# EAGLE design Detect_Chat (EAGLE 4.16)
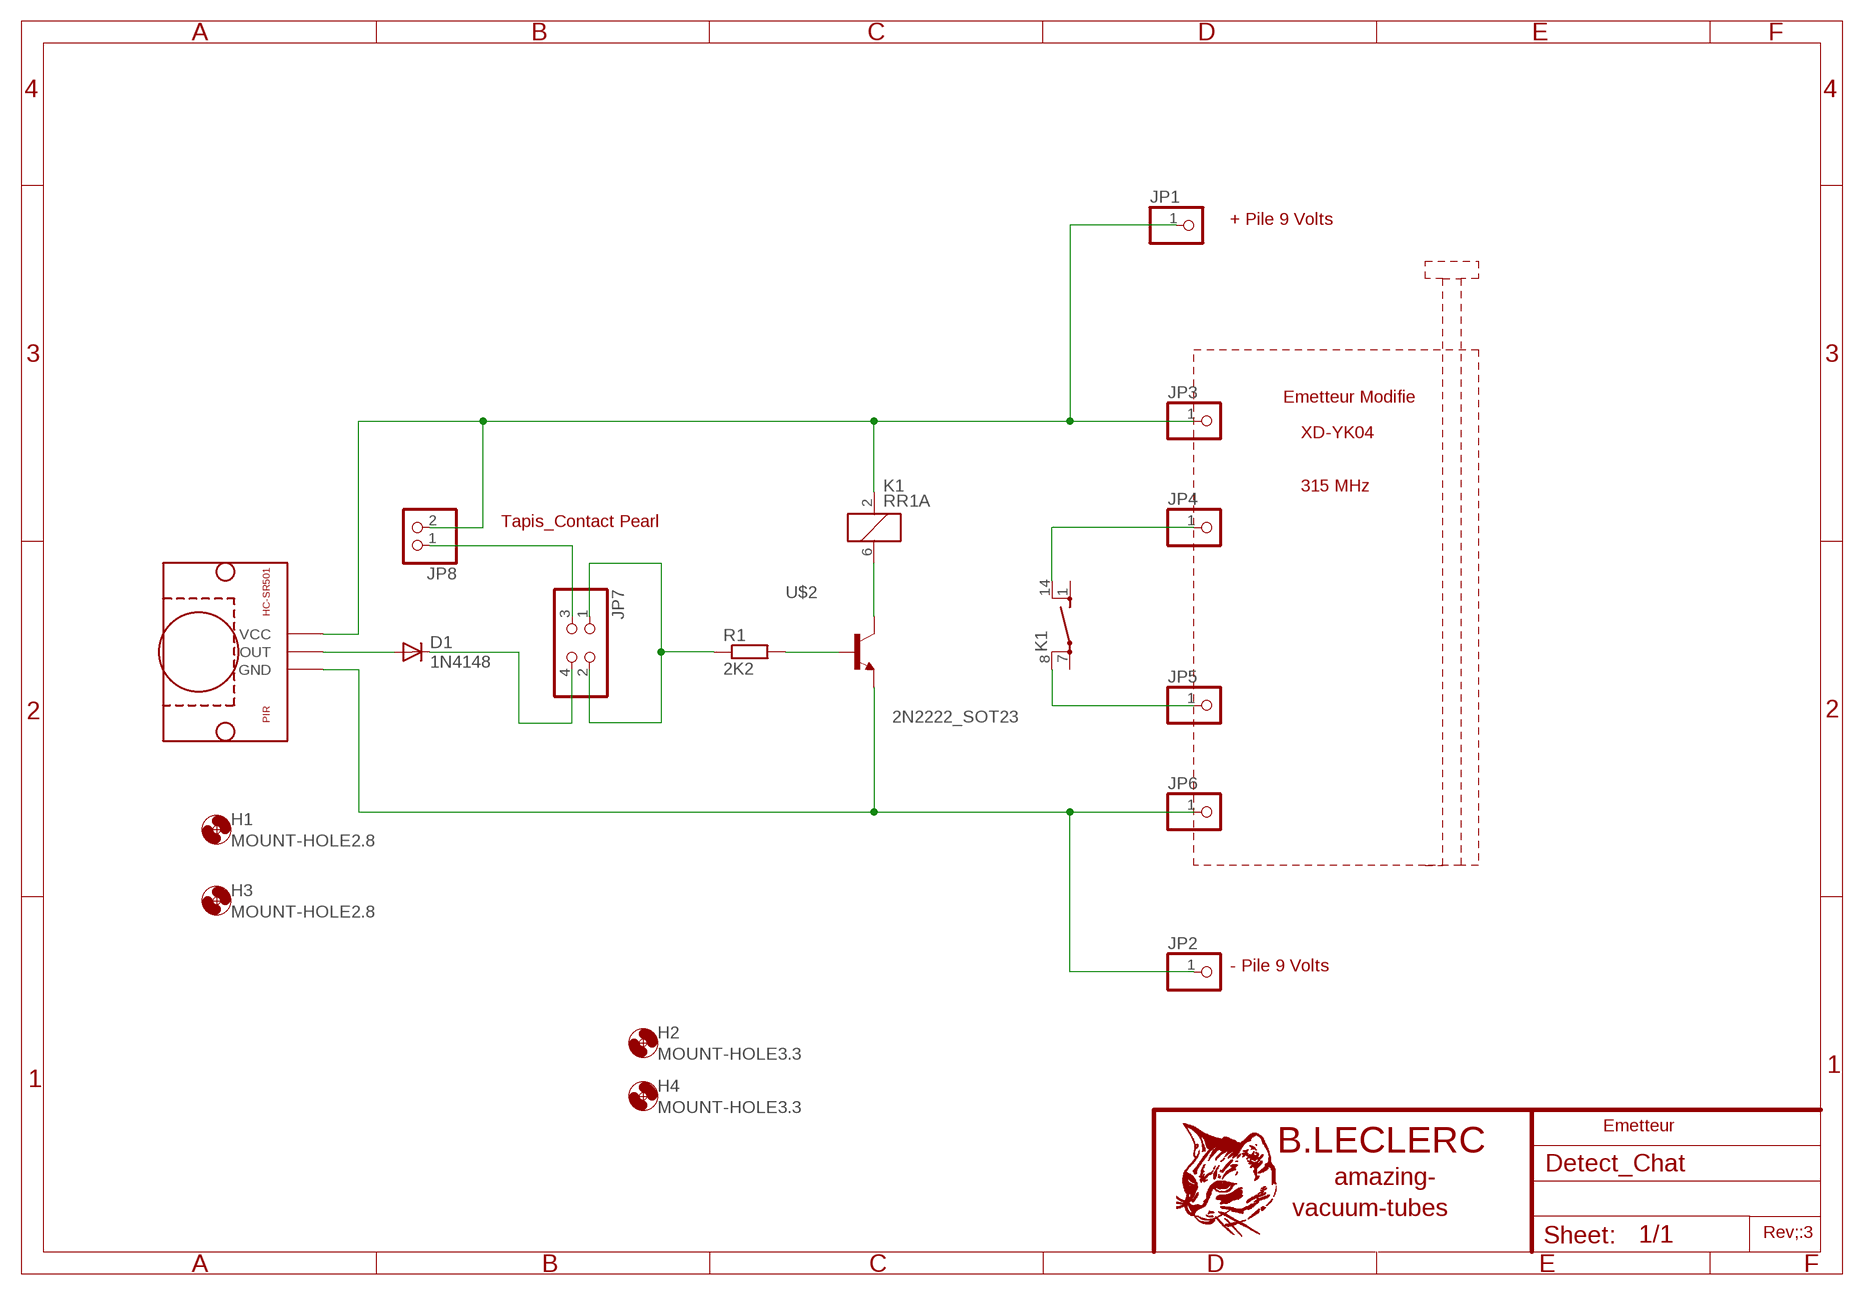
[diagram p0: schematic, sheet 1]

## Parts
D1  1N4148  DIODE-DO214AA  [DO214AA]
H1  MOUNT-HOLE2.8  [2,8]
H2  MOUNT-HOLE3.3  [3,3]
H3  MOUNT-HOLE2.8  [2,8]
H4  MOUNT-HOLE3.3  [3,3]
JP1  PINHD-1X1  [1X01]
JP2  PINHD-1X1  [1X01]
JP3  PINHD-1X1  [1X01]
JP4  PINHD-1X1  [1X01]
JP5  PINHD-1X1  [1X01]
JP6  PINHD-1X1  [1X01]
JP7  PINHD-2X2  [2X02]
JP8  PINHD-1X2  [1X02]
K1  RR1A  [RR1A]
R1  2K2  R-EU_M1206  [M1206]
U$2  2N2222_SOT23  [SOT23-BEC]
U$3  PIR_HC-SR501  [HC-SR501PIR]

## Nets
GND: JP2.1 JP6.1 U$2.E U$3.GND
N$1: D1.A U$3.OUT
N$2: JP7.1 JP7.2 R1.1
N$3: R1.2 U$2.B
N$4: K1.6 U$2.C
N$5: D1.C JP7.4
N$6: JP5.1 K1.8(2:P)
N$7: JP4.1 K1.14(2:S)
N$8: JP7.3 JP8.1
VCC: JP1.1 JP3.1 JP8.2 K1.2 U$3.VCC
Unconnected: K1.1(2:S) K1.7(2:P)

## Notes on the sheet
- + Pile 9 Volts
- Emetteur Modifie
- XD-YK04
- 315 MHz
- Tapis_Contact Pearl
- - Pile 9 Volts
- Emetteur
- Rev;:3

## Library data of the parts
D1 = diode:DIODE-: DIODE
H1-H4 = holes:MOUNT-HOLE: MOUNTING HOLE with drill center marker
JP1-JP6 = pinhead:PINHD-1X1: PIN HEADER
JP7 = pinhead:PINHD-2X2: PIN HEADER
JP8 = pinhead:PINHD-1X2: PIN HEADER
K1 = relay:RR1A: RELAY reed, polarity, 1 x norm. open with shield
R1 = rcl:R-EU_: RESISTOR, European symbol
U$2 = transistor:2N2222_SOT23
U$3 = Arduino:PIR_HC-SR501

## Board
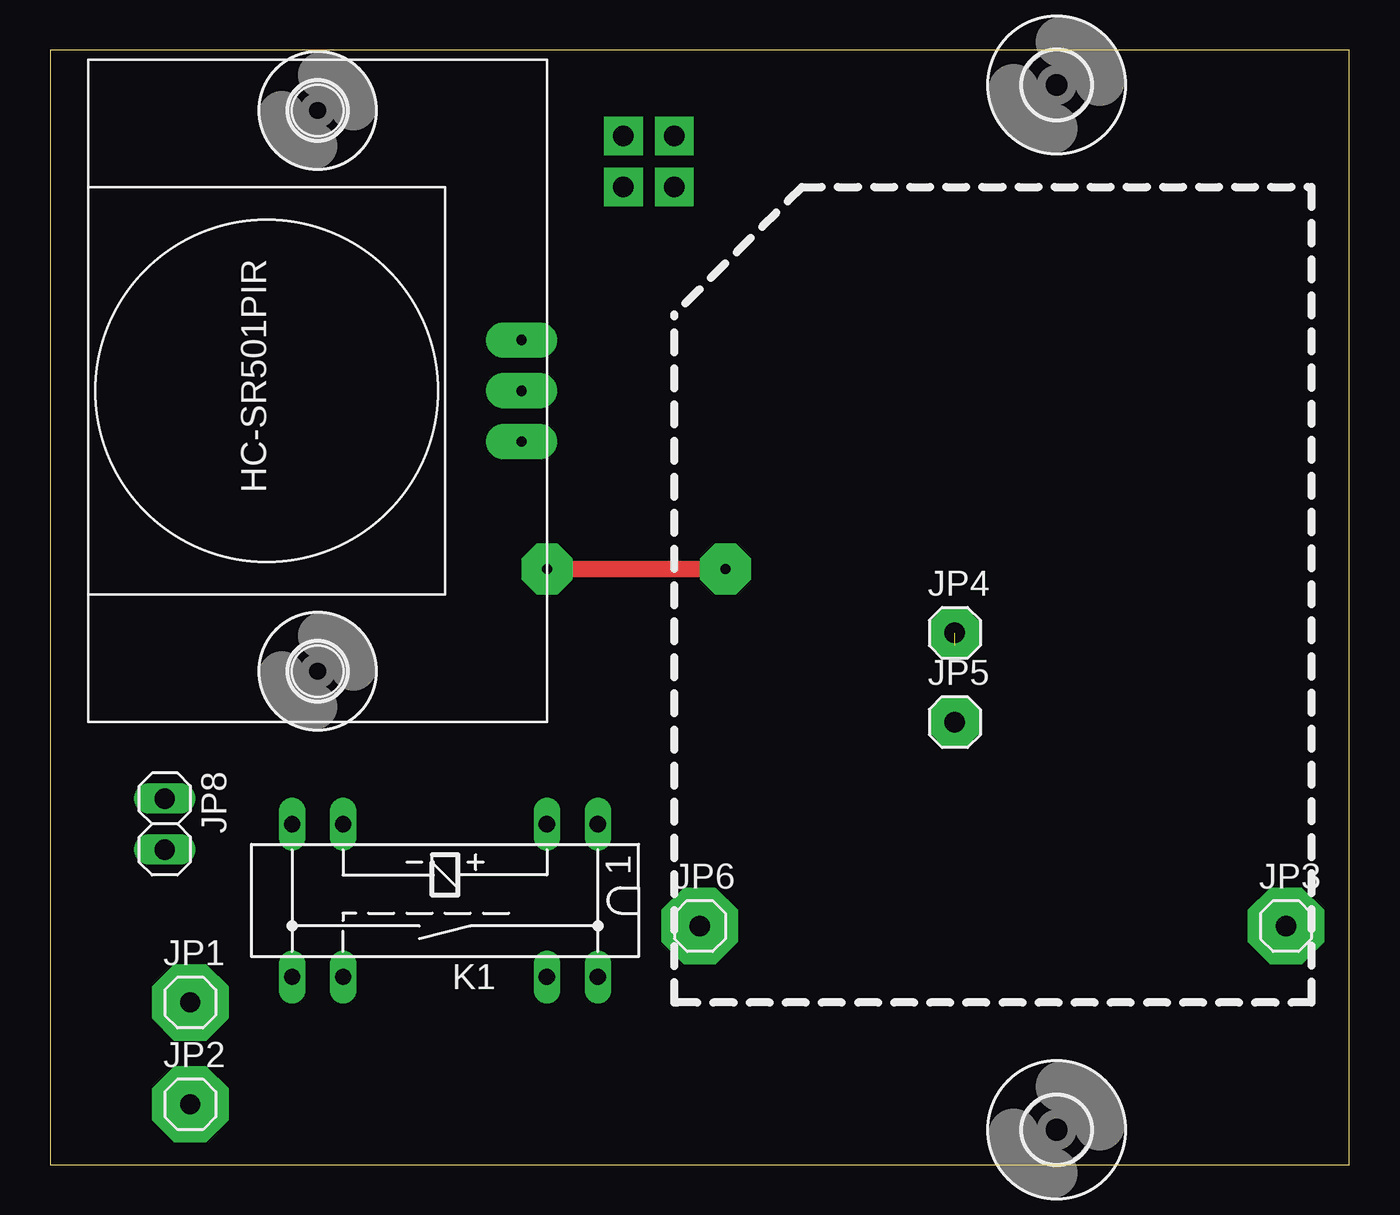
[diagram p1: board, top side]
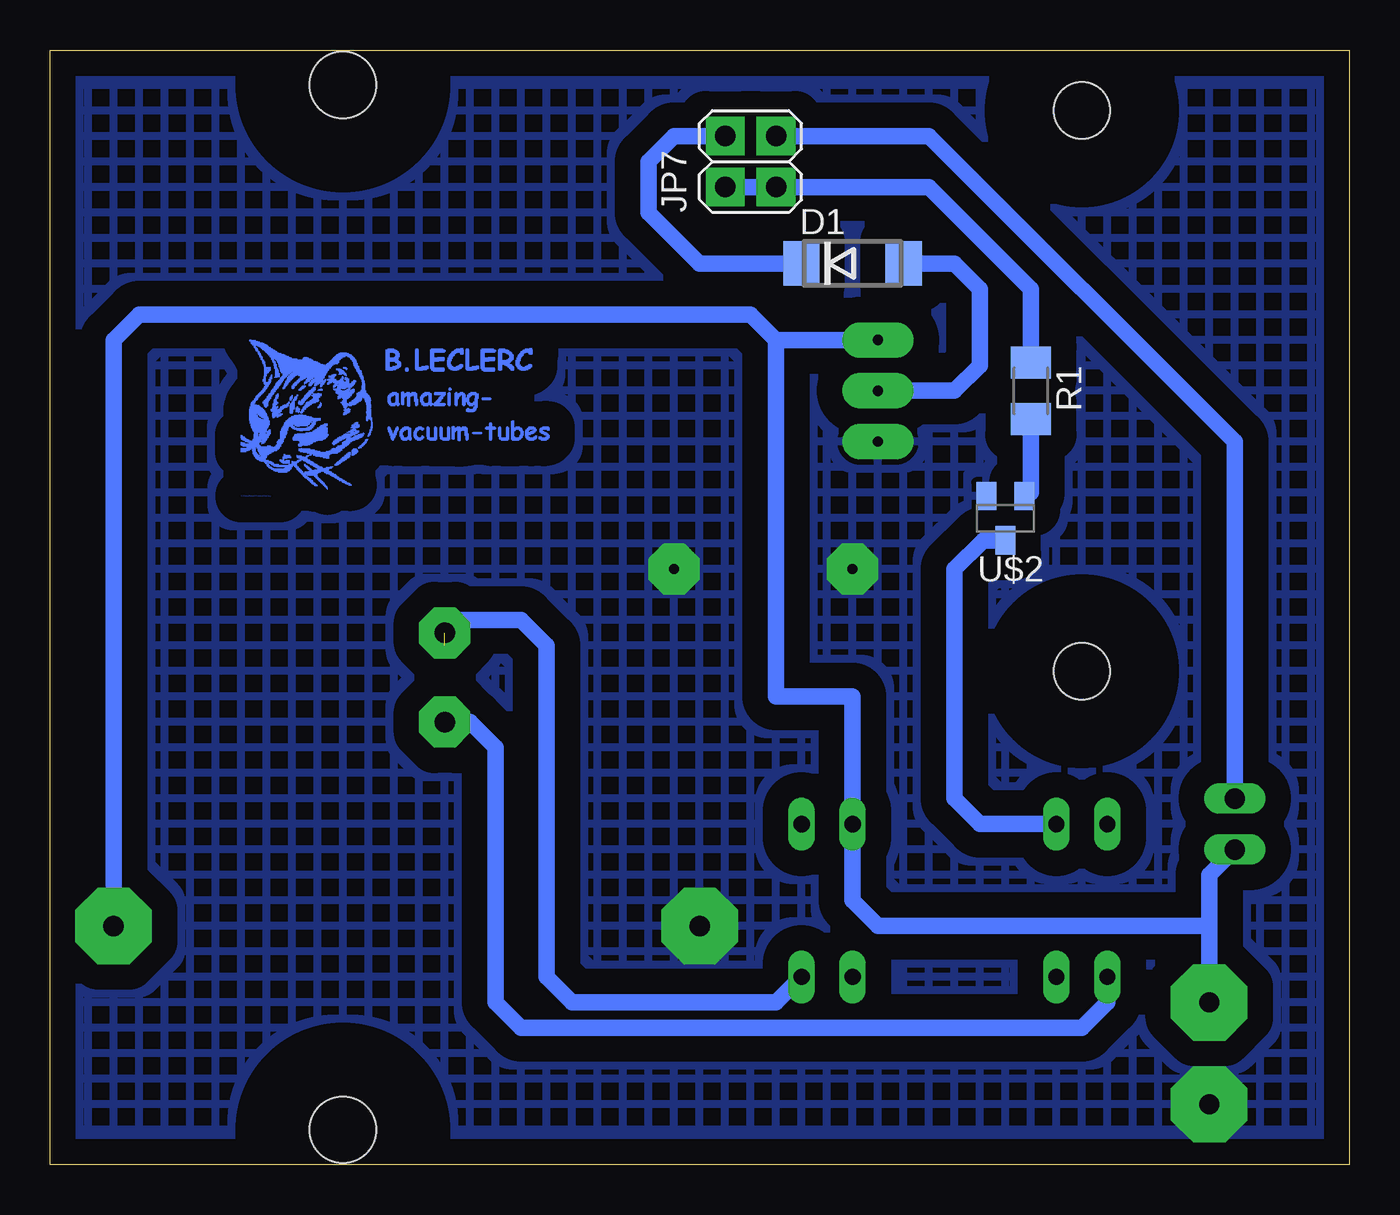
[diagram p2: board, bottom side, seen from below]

Size 64.75 x 55.55 mm. Coordinates in mm from the lower left corner, seen from the top.
Outline: 0,0 64.75,0 64.75,55.55 0,55.55 0,0
Copper layers (1*16): Top 0.035mm / dielectric 1.5mm / Bottom 0.035mm
Design rules "default": minimum track width 10mil, minimum drill 24mil, track to track 8mil, track to pad 8mil, pad to pad 8mil, via to via 8mil, smd to smd 8mil, copper to edge 40mil, drill to drill 8mil, minimum pad ring 10mil, minimum via ring 8mil, stop-mask expansion 4mil, vias tented up to drill 0mil, thermal gap 10mil

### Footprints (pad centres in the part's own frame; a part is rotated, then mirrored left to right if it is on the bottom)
DO214AA = smd 1.8 x 2.2: A 2.55,0; C -2.55,0
2,8 = hole 2.8: 0,0
3,3 = hole 3.3: 0,0
1X01 = drill 1.016 octagon: 1 0,0
2X02 = drill 1.016 octagon: 1 -1.27,-1.27; 2 -1.27,1.27; 3 1.27,-1.27; 4 1.27,1.27
1X02 = drill 1.016 long: 1 -1.27,0; 2 1.27,0
RR1A = drill 0.813 long: 1 -7.62,-3.81; 2 -5.08,-3.81; 6 5.08,-3.81; 7 7.62,-3.81; 8 7.62,3.81; 9 5.08,3.81; 13 -5.08,3.81; 14 -7.62,3.81
M1206 = smd 1.6 x 2: 1 -1.4,0; 2 1.4,0
SOT23-BEC = smd 1 x 1.4: B -0.95,-1.1; C 0,1.1; E 0.95,-1.1
HC-SR501PIR = drill 0.5 pad 1.778 long: GND -2.54,-10.16; OUT 0,-10.16; VCC 2.54,-10.16

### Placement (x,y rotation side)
D1  24.76,44.92 0 bottom
H1  13.33,24.6 0 top
H2  50.16,53.81 0 top
H3  13.33,52.54 0 top
H4  50.16,1.74 0 top
JP1  6.98,8.09 0 top
JP2  6.98,3.01 0 top
JP3  61.59,11.9 0 top
JP4  45.08,26.5 0 top
JP5  45.08,22.06 0 top
JP6  32.38,11.9 0 top
JP7  29.84,50 90 bottom
JP8  5.71,16.98 270 top
K1  19.68,13.17 180 top
R1  15.87,38.57 270 bottom
U$2  17.14,32.22 180 bottom
U$3  13.33,38.57 90 top
U$4  [CHAT]  55.24,33.49 0 bottom

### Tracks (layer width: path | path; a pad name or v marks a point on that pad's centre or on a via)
GND  (via drill 0.5 pad 2.54, 0.5 pad 3.81)
  Top 0.813: v24.76,29.68 v33.65,29.68
  other vias: 32.38,11.9 6.98,3.01
  pour Bottom (isolate 1.27, hatched): 0.63,55.08 64.13,55.08 64.13,0.47 0.63,0.47
N$1
  Bottom 0.406: D1.A
  Bottom 0.813: U$3.OUT 19.68,38.57 18.41,39.84 18.41,43.65 19.68,44.92 D1.A
N$2
  Bottom 0.813: JP7.2 JP7.1 20.95,48.73 15.87,43.65 R1.1 15.87,39.84
N$3
  Bottom 0.406: 15.87,33.49 16.04,33.32 U$2.B
  Bottom 0.813: 15.87,33.49 R1.2
N$4  (via drill 0.5 pad 1.27)
  Bottom 0.813: K1.6 18.41,16.98 19.68,18.25 19.68,29.68 18.24,31.12 U$2.C
  other vias: 14.6,16.98
N$5
  Bottom 0.813: D1.C 32.38,44.92 34.92,47.46 34.92,50 33.65,51.27 JP7.4
N$6  (via drill 0.5 pad 1.27, 0.5 pad 2.54)
  Bottom 0.813: K1.8 12.06,8.09 13.33,6.82 41.27,6.82 42.54,8.09 42.54,20.79 43.81,22.06 JP5.1
  other vias: 45.08,22.06 12.06,9.36
N$7  (via drill 0.5 pad 1.27, 0.5 pad 2.54)  (1 unrouted)
  Bottom 0.406: 45.08,27.14 45.08,25.87
  Bottom 0.813: 45.08,27.14 41.27,27.14 40,25.87 40,9.36 38.73,8.09 28.57,8.09 K1.14
  other vias: 45.08,26.5 27.3,9.36
N$8
  Bottom 0.813: JP8.1 5.71,36.03 20.95,51.27 JP7.3
N$9  (via drill 0.5 pad 1.27)
  other vias: 5.71,18.25
N$10  (via drill 0.5 pad 1.27)
  other vias: 12.06,16.98
N$11  (via drill 0.5 pad 1.27)
  other vias: 5.71,15.71
N$12  (via drill 0.5 pad 1.27)
  other vias: 24.76,9.36
N$13  (via drill 0.5 pad 1.27)
  other vias: 14.6,9.36
N$14  (via drill 0.5 pad 3.81)
  other vias: 6.98,8.09
N$16  (via drill 0.5 pad 1.93)
  other vias: 28.57,51.27
N$17  (via drill 0.5 pad 1.27)
  other vias: 27.3,16.98
N$18  (via drill 0.5 pad 1.93)
  other vias: 28.57,48.73
N$19  (via drill 0.5 pad 1.93)
  other vias: 31.11,51.27
N$20  (via drill 0.5 pad 1.93)
  other vias: 31.11,48.73
VCC  (via drill 0.5 pad 1.27, 0.5 pad 3.81)
  Bottom 0.813: 28.57,41.11 U$3.VCC | 28.57,41.11 28.57,23.33 24.76,23.33 K1.2 24.76,13.17 23.49,11.9 6.98,11.9 | JP3.1 61.59,41.11 60.32,42.38 29.84,42.38 28.57,41.11 | JP1.1 6.98,11.9 | JP8.2 6.98,14.44 6.98,11.9
  other vias: 61.59,11.9 24.76,16.98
